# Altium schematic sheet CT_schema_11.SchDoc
size 382 x 278 mm
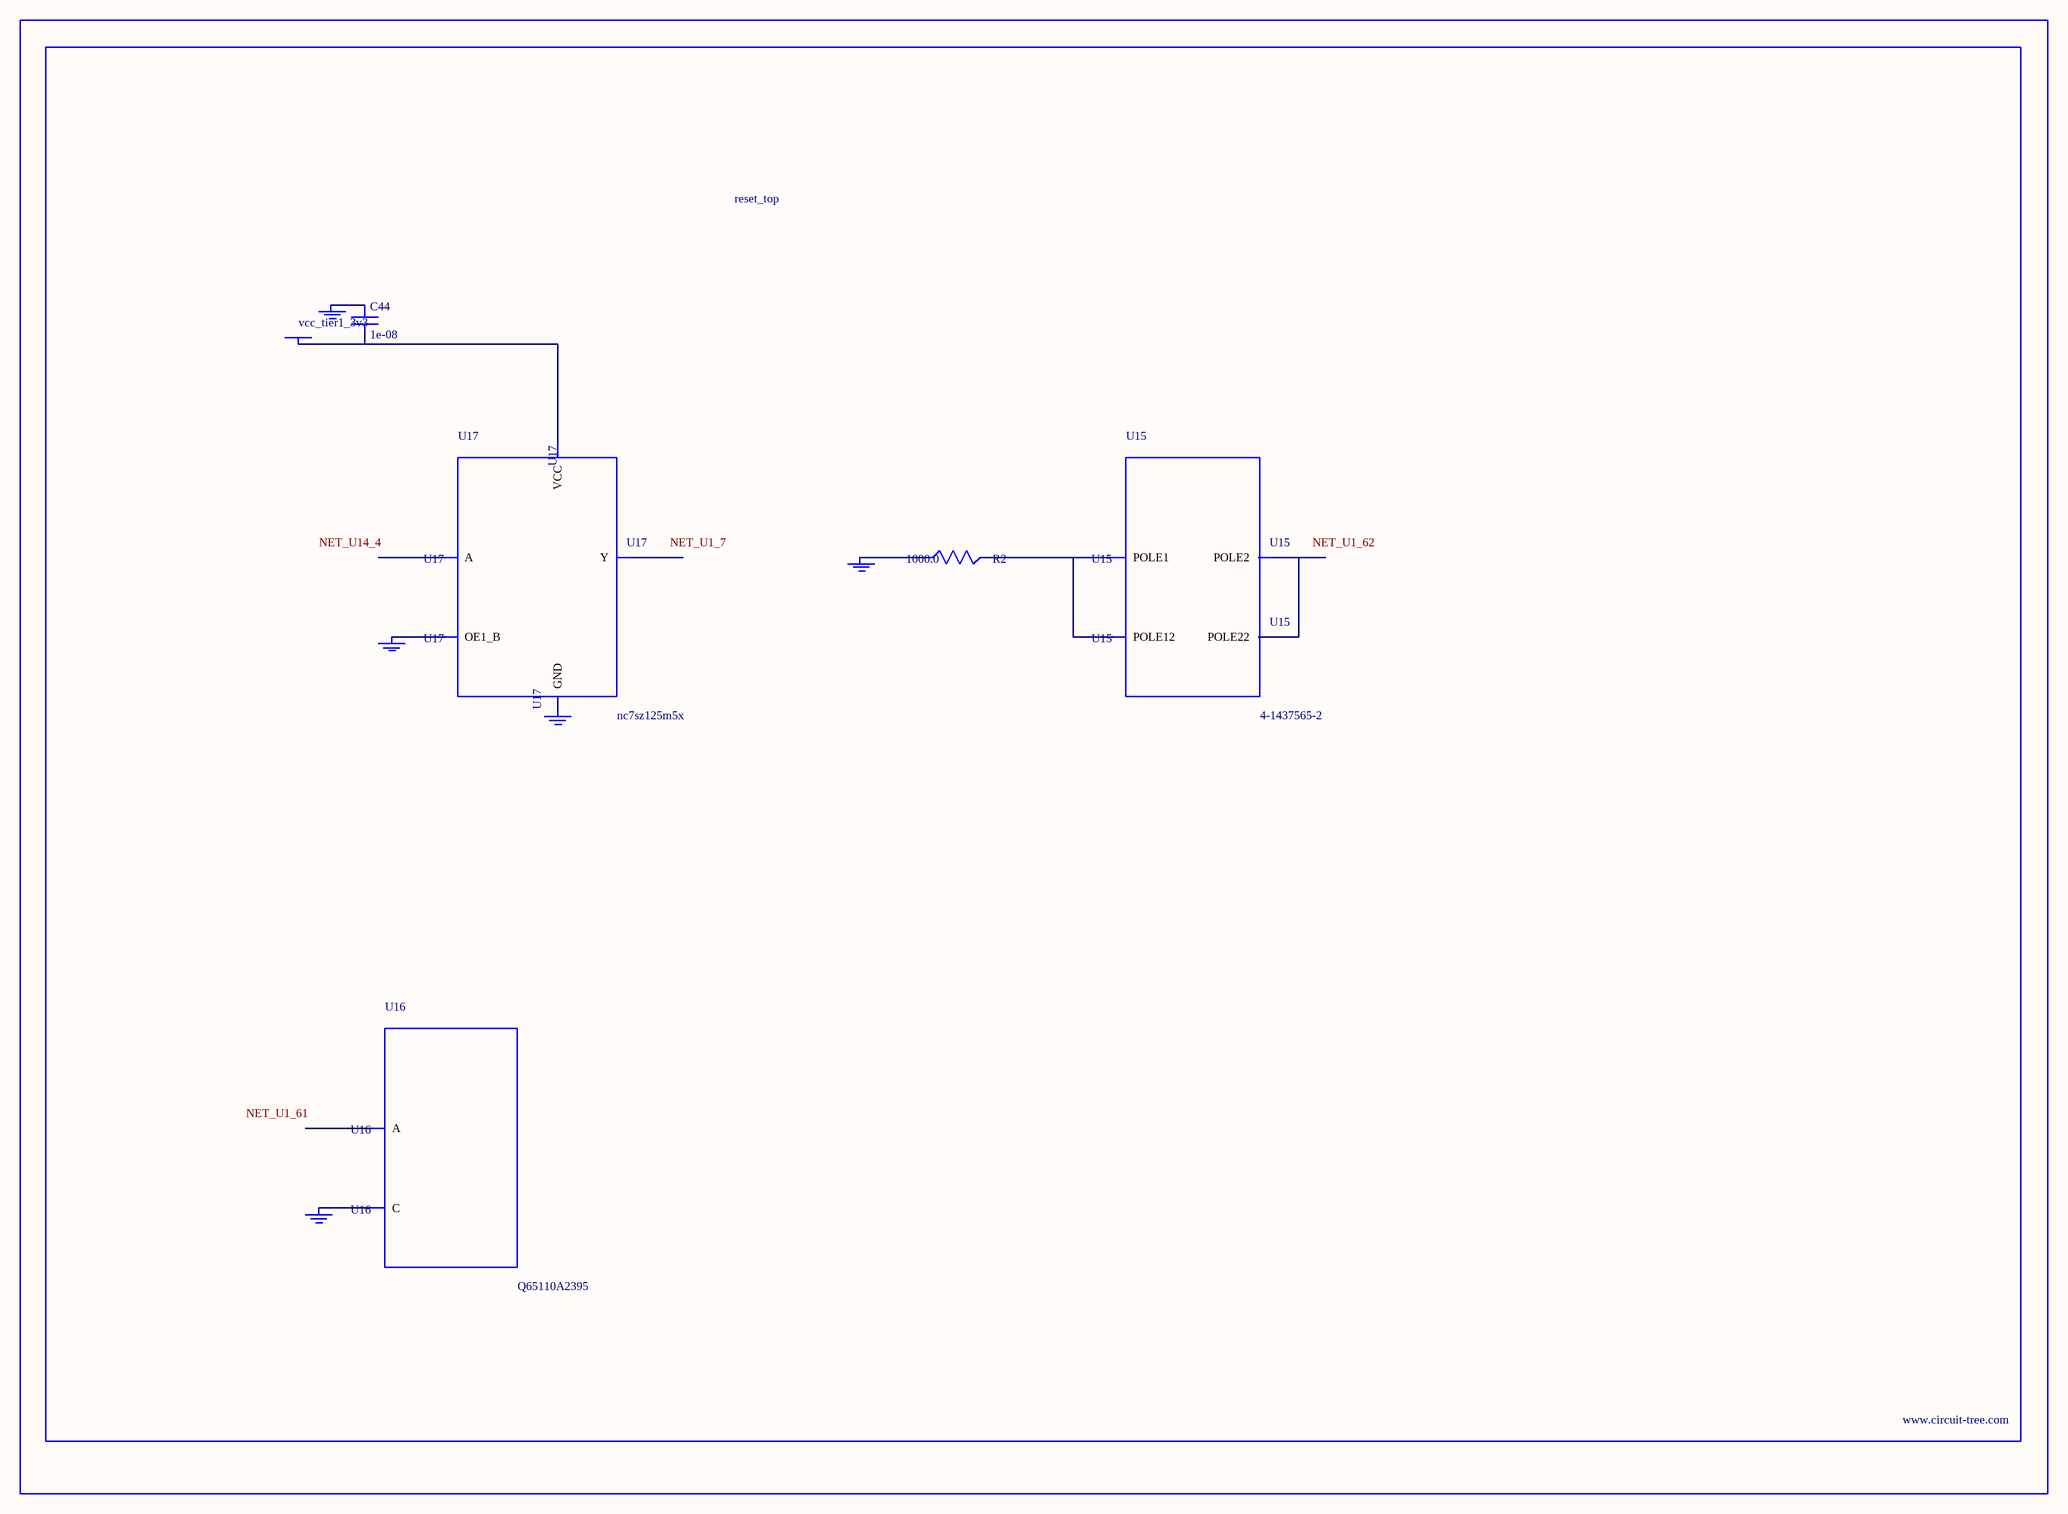
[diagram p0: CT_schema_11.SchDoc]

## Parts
BORDER10  (no value)
C44  1e-08  [C0402]
GND_INSTANCE_10_0  (no value)
GND_INSTANCE_10_1  (no value)
GND_INSTANCE_10_2  (no value)
GND_INSTANCE_10_3  (no value)
GND_INSTANCE_10_4  (no value)
POWER_INSTANCE_10_0  vcc_tier1_3v3
R2  1000.0  [R0603]
U15  4-1437565-2  [SW_4-1437565-2]
U16  Q65110A2395  [LGM67K-G1J2-24-Z]
U17  nc7sz125m5x  [NC7SZ125M5X]

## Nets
NetC44_1: C44.1 GND_INSTANCE_10_2.0(GND)
NetC44_2: C44.2 POWER_INSTANCE_10_0.0(PWR) U17.5(VCC)
NetGND_INSTANCE_10_0_0: GND_INSTANCE_10_0.0(GND) R2.1
NetGND_INSTANCE_10_1_0: GND_INSTANCE_10_1.0(GND) U16.C
NetGND_INSTANCE_10_3_0: GND_INSTANCE_10_3.0(GND) U17.1(OE1_B)
NetGND_INSTANCE_10_4_0: GND_INSTANCE_10_4.0(GND) U17.3(GND)
NetR2_2: R2.2 U15.1(POLE1) U15.2(POLE12)
NetU15_3: U15.3(POLE2) U15.4(POLE22)

Not connected (* = marked no-connect by the designer): U16 A; U17 2(A) 4(Y)

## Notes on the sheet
- Labels drawn without touching a wire or pin: NET_U1_7, NET_U1_61, NET_U1_62, NET_U14_4

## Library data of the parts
BORDER10 = BORDER_PAGE10
C44 = C0402C103K3RAC
GND_INSTANCE_10_0-GND_INSTANCE_10_4 = GND
POWER_INSTANCE_10_0 = PWR
R2 = RC0603JR-071KL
